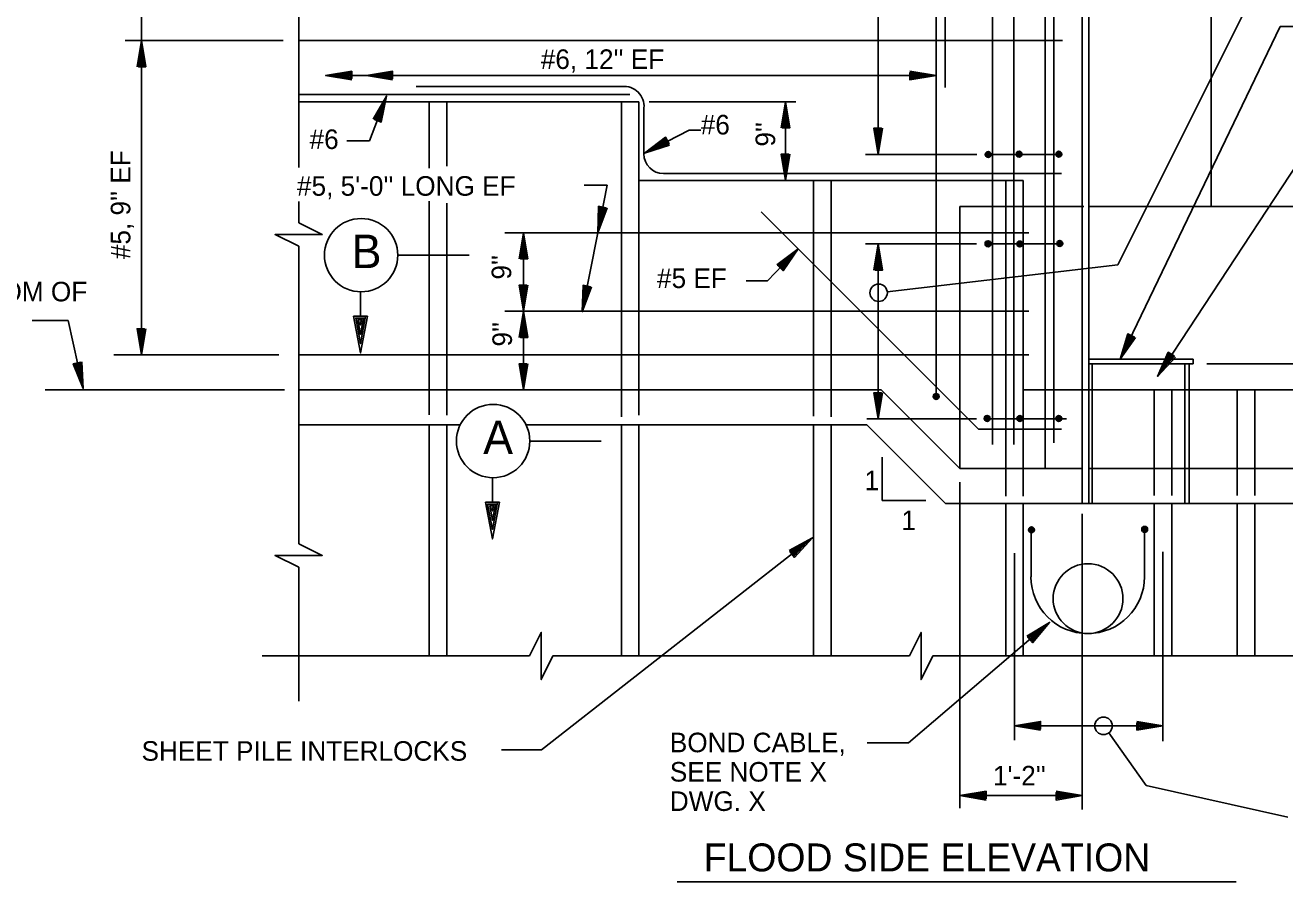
# Model space of a CAD drawing. Extents: x 22369.6 to 22428.3, y 22369.6 to 22415.
# Drawn here: x 22390.66 to 22402.68, y 22392.31 to 22400.49 of the extents above; entities that cross this region are included whole.
import ezdxf

# ---------------------------------------------------------------- set-up
doc = ezdxf.new("R2010")
doc.units = 0
for name, color, linetype in [('Level 1', 7, 'Continuous'), ('Level 10', 7, 'Continuous'), ('Level 2', 7, 'Continuous'), ('Level 3', 7, 'Continuous'), ('Level 4', 7, 'Continuous'), ('Level 7', 7, 'Continuous')]:
    doc.layers.add(name, color=color, linetype=linetype)

msp = doc.modelspace()

# ---------------------------------------------------------------- linework, layer by layer
at = {"layer": 'Level 1'}
for p, q in [((22398.803, 22399.253), (22398.803, 22404.537)), ((22393.273, 22402.402), (22393.273, 22399.126)), ((22401.087, 22398.198), (22402.551, 22401.125)), ((22391.773, 22400.339), (22391.773, 22400.88)), ((22401.112, 22397.297), (22402.638, 22400.474)), ((22402.638, 22400.474), (22403.065, 22400.474)), ((22393.126, 22400.339), (22391.617, 22400.339)), ((22391.773, 22397.339), (22391.773, 22400.339)), ((22391.773, 22400.339), (22391.773, 22400.339)), ((22391.773, 22400.269), (22391.773, 22400.269)), ((22393.53, 22400.005), (22393.53, 22400.005)), ((22393.53, 22400.005), (22399.355, 22400.005)), ((22393.6, 22400.005), (22393.6, 22400.005)), ((22394.125, 22400.005), (22394.125, 22400.005)), ((22394.148, 22400.02), (22394.148, 22400.02)), ((22394.148, 22400.001), (22394.148, 22400.001)), ((22394.158, 22400.033), (22394.158, 22400.033)), ((22394.158, 22399.988), (22394.158, 22399.988)), ((22394.169, 22400.046), (22394.169, 22400.046)), ((22394.169, 22399.976), (22394.169, 22399.976)), ((22394.169, 22399.964), (22394.169, 22399.964)), ((22399.285, 22400.005), (22399.285, 22400.005)), ((22399.355, 22400.005), (22399.355, 22400.005)), ((22401.468, 22397.133), (22403.245, 22399.842)), ((22393.949, 22399.381), (22394.111, 22399.809)), ((22394.086, 22399.744), (22394.086, 22399.744)), ((22394.111, 22399.809), (22394.111, 22399.809)), ((22396.616, 22399.755), (22398.017, 22399.755)), ((22397.918, 22399.005), (22397.918, 22399.755)), ((22397.918, 22399.755), (22397.918, 22399.755)), ((22397.918, 22399.686), (22397.918, 22399.686)), ((22396.571, 22399.265), (22396.999, 22399.485)), ((22396.999, 22399.485), (22397.109, 22399.485)), ((22393.731, 22399.381), (22393.949, 22399.381)), ((22396.571, 22399.265), (22396.571, 22399.265)), ((22396.633, 22399.297), (22396.633, 22399.297)), ((22399.743, 22399.253), (22398.681, 22399.253)), ((22398.803, 22399.323), (22398.803, 22399.323)), ((22398.803, 22399.253), (22398.803, 22399.253)), ((22397.918, 22399.075), (22397.918, 22399.075)), ((22397.918, 22399.005), (22397.918, 22399.005)), ((22395.998, 22398.959), (22396.217, 22398.959)), ((22396.127, 22398.505), (22396.217, 22398.959)), ((22393.273, 22398.6), (22393.273, 22398.804)), ((22396.141, 22398.573), (22396.141, 22398.573)), ((22395.418, 22397.755), (22395.418, 22398.505)), ((22395.418, 22398.505), (22395.418, 22398.505)), ((22395.418, 22398.436), (22395.418, 22398.436)), ((22395.979, 22397.751), (22396.127, 22398.505)), ((22396.127, 22398.505), (22396.127, 22398.505)), ((22399.739, 22398.399), (22398.681, 22398.399)), ((22398.803, 22396.729), (22398.803, 22398.399)), ((22398.803, 22398.399), (22398.803, 22398.399)), ((22393.273, 22395.537), (22393.273, 22398.376)), ((22397.747, 22398.046), (22398.037, 22398.351)), ((22397.989, 22398.301), (22397.989, 22398.301)), ((22398.037, 22398.351), (22398.037, 22398.351)), ((22398.803, 22398.329), (22398.803, 22398.329)), ((22398.889, 22397.941), (22401.087, 22398.198)), ((22397.542, 22398.046), (22397.747, 22398.046)), ((22395.418, 22397.825), (22395.418, 22397.825)), ((22395.992, 22397.819), (22395.992, 22397.819)), ((22395.418, 22397.005), (22395.418, 22397.755)), ((22395.418, 22397.755), (22395.418, 22397.755)), ((22395.418, 22397.755), (22395.418, 22397.755)), ((22395.418, 22397.686), (22395.418, 22397.686)), ((22395.979, 22397.751), (22395.979, 22397.751)), ((22390.732, 22397.666), (22391.074, 22397.666)), ((22391.074, 22397.666), (22391.217, 22397.019)), ((22393.083, 22397.339), (22391.508, 22397.339)), ((22391.773, 22397.408), (22391.773, 22397.408)), ((22391.773, 22397.339), (22391.773, 22397.339)), ((22401.142, 22397.36), (22401.142, 22397.36)), ((22400.811, 22397.297), (22401.807, 22397.297)), ((22400.811, 22397.255), (22401.807, 22397.255)), ((22400.843, 22395.922), (22400.843, 22397.255)), ((22401.112, 22397.297), (22401.112, 22397.297)), ((22401.506, 22397.191), (22401.506, 22397.191)), ((22401.728, 22395.922), (22401.728, 22397.255)), ((22401.769, 22395.922), (22401.769, 22397.255)), ((22401.807, 22397.255), (22401.807, 22397.297)), ((22401.938, 22397.255), (22404.364, 22397.255)), ((22391.202, 22397.087), (22391.202, 22397.087)), ((22395.418, 22397.075), (22395.418, 22397.075)), ((22401.468, 22397.133), (22401.468, 22397.133)), ((22393.137, 22397.005), (22390.853, 22397.005)), ((22391.217, 22397.019), (22391.217, 22397.019)), ((22395.418, 22397.005), (22395.418, 22397.005)), ((22399.739, 22396.729), (22398.693, 22396.729)), ((22398.803, 22396.798), (22398.803, 22396.798)), ((22398.803, 22396.729), (22398.803, 22396.729)), ((22399.582, 22396.123), (22399.582, 22393.012)), ((22400.749, 22395.821), (22400.749, 22393.002)), ((22395.59, 22393.569), (22398.174, 22395.594)), ((22398.12, 22395.551), (22398.12, 22395.551)), ((22398.174, 22395.594), (22398.174, 22395.594)), ((22400.103, 22395.447), (22400.103, 22393.662)), ((22401.519, 22395.459), (22401.519, 22393.652)), ((22393.273, 22394.036), (22393.273, 22395.313)), ((22400.437, 22394.786), (22399.09, 22393.636)), ((22400.384, 22394.741), (22400.384, 22394.741)), ((22400.437, 22394.786), (22400.437, 22394.786)), ((22392.926, 22394.466), (22395.475, 22394.466)), ((22395.699, 22394.466), (22399.1, 22394.466)), ((22399.324, 22394.466), (22405.542, 22394.466)), ((22400.103, 22393.799), (22401.519, 22393.799)), ((22400.103, 22393.799), (22400.103, 22393.799)), ((22400.172, 22393.799), (22400.172, 22393.799)), ((22401.001, 22393.732), (22401.36, 22393.23)), ((22401.45, 22393.799), (22401.45, 22393.799)), ((22401.519, 22393.799), (22401.519, 22393.799)), ((22398.697, 22393.636), (22399.09, 22393.636)), ((22395.209, 22393.569), (22395.59, 22393.569)), ((22401.36, 22393.23), (22402.709, 22392.927)), ((22399.582, 22393.133), (22400.749, 22393.133)), ((22399.582, 22393.133), (22399.582, 22393.133)), ((22399.651, 22393.133), (22399.651, 22393.133)), ((22400.679, 22393.133), (22400.679, 22393.133)), ((22400.749, 22393.133), (22400.749, 22393.133))]:
    msp.add_line(p, q, dxfattribs=at)
for points in [[(22391.732, 22400.089), (22391.773, 22400.339), (22391.814, 22400.089), (22391.744, 22400.089), (22391.773, 22400.269), (22391.801, 22400.1), (22391.756, 22400.1), (22391.773, 22400.203), (22391.788, 22400.111), (22391.769, 22400.111), (22391.773, 22400.133)], [(22393.78, 22399.964), (22393.53, 22400.005), (22393.78, 22400.046), (22393.78, 22399.976), (22393.6, 22400.005), (22393.769, 22400.033), (22393.769, 22399.988), (22393.666, 22400.005), (22393.758, 22400.02), (22393.758, 22400.001), (22393.736, 22400.005)], [(22394.169, 22399.964), (22393.92, 22400.005), (22394.169, 22400.046), (22394.169, 22399.976), (22393.989, 22400.005), (22394.158, 22400.033), (22394.158, 22399.988), (22394.056, 22400.005), (22394.148, 22400.02), (22394.148, 22400.001), (22394.125, 22400.005)], [(22399.105, 22400.046), (22399.355, 22400.005), (22399.105, 22399.964), (22399.105, 22400.034), (22399.285, 22400.005), (22399.116, 22399.977), (22399.116, 22400.022), (22399.219, 22400.005), (22399.127, 22399.99), (22399.127, 22400.009), (22399.149, 22400.005)], [(22393.984, 22399.59), (22394.111, 22399.809), (22394.061, 22399.561), (22393.995, 22399.586), (22394.086, 22399.744), (22394.053, 22399.576), (22394.01, 22399.592), (22394.063, 22399.682), (22394.044, 22399.591), (22394.027, 22399.597), (22394.038, 22399.617)], [(22397.877, 22399.506), (22397.918, 22399.755), (22397.959, 22399.506), (22397.889, 22399.506), (22397.918, 22399.686), (22397.946, 22399.517), (22397.901, 22399.517), (22397.918, 22399.619), (22397.933, 22399.527), (22397.914, 22399.527), (22397.918, 22399.55)], [(22398.844, 22399.503), (22398.803, 22399.253), (22398.761, 22399.503), (22398.832, 22399.503), (22398.803, 22399.323), (22398.775, 22399.492), (22398.82, 22399.492), (22398.803, 22399.389), (22398.788, 22399.481), (22398.807, 22399.481), (22398.803, 22399.459)], [(22396.812, 22399.342), (22396.571, 22399.265), (22396.774, 22399.416), (22396.807, 22399.353), (22396.633, 22399.297), (22396.771, 22399.399), (22396.792, 22399.359), (22396.692, 22399.327), (22396.767, 22399.382), (22396.776, 22399.366), (22396.754, 22399.359)], [(22397.959, 22399.255), (22397.918, 22399.005), (22397.877, 22399.255), (22397.947, 22399.255), (22397.918, 22399.075), (22397.89, 22399.244), (22397.935, 22399.244), (22397.918, 22399.141), (22397.903, 22399.233), (22397.922, 22399.233), (22397.918, 22399.211)], [(22396.216, 22398.742), (22396.127, 22398.505), (22396.135, 22398.758), (22396.204, 22398.744), (22396.141, 22398.573), (22396.146, 22398.745), (22396.19, 22398.736), (22396.154, 22398.639), (22396.157, 22398.732), (22396.175, 22398.728), (22396.167, 22398.707)], [(22393.273, 22398.376), (22393.048, 22398.487), (22393.498, 22398.487), (22393.273, 22398.6)], [(22395.377, 22398.256), (22395.418, 22398.505), (22395.459, 22398.256), (22395.389, 22398.256), (22395.418, 22398.436), (22395.446, 22398.267), (22395.401, 22398.267), (22395.418, 22398.369), (22395.433, 22398.277), (22395.414, 22398.277), (22395.418, 22398.3)], [(22398.761, 22398.149), (22398.803, 22398.399), (22398.844, 22398.149), (22398.773, 22398.149), (22398.803, 22398.329), (22398.831, 22398.16), (22398.785, 22398.16), (22398.803, 22398.263), (22398.817, 22398.171), (22398.799, 22398.171), (22398.803, 22398.193)], [(22397.835, 22398.199), (22398.037, 22398.351), (22397.895, 22398.142), (22397.844, 22398.191), (22397.989, 22398.301), (22397.893, 22398.159), (22397.86, 22398.19), (22397.943, 22398.253), (22397.891, 22398.176), (22397.877, 22398.189), (22397.896, 22398.202)], [(22395.459, 22398.005), (22395.418, 22397.755), (22395.377, 22398.005), (22395.447, 22398.005), (22395.418, 22397.825), (22395.39, 22397.994), (22395.435, 22397.994), (22395.418, 22397.891), (22395.403, 22397.983), (22395.422, 22397.983), (22395.418, 22397.961)], [(22396.068, 22397.988), (22395.979, 22397.751), (22395.986, 22398.004), (22396.056, 22397.99), (22395.992, 22397.819), (22395.997, 22397.991), (22396.042, 22397.982), (22396.005, 22397.885), (22396.008, 22397.978), (22396.027, 22397.974), (22396.018, 22397.953)], [(22395.377, 22397.506), (22395.418, 22397.755), (22395.459, 22397.506), (22395.389, 22397.506), (22395.418, 22397.686), (22395.446, 22397.517), (22395.401, 22397.517), (22395.418, 22397.619), (22395.433, 22397.527), (22395.414, 22397.527), (22395.418, 22397.55)], [(22391.814, 22397.588), (22391.773, 22397.339), (22391.732, 22397.588), (22391.802, 22397.588), (22391.773, 22397.408), (22391.745, 22397.577), (22391.79, 22397.577), (22391.773, 22397.475), (22391.758, 22397.567), (22391.777, 22397.567), (22391.773, 22397.544)], [(22401.258, 22397.504), (22401.112, 22397.297), (22401.183, 22397.54), (22401.247, 22397.509), (22401.142, 22397.36), (22401.191, 22397.524), (22401.231, 22397.505), (22401.171, 22397.42), (22401.198, 22397.509), (22401.215, 22397.501), (22401.201, 22397.482)], [(22401.639, 22397.319), (22401.468, 22397.133), (22401.57, 22397.364), (22401.629, 22397.326), (22401.506, 22397.191), (22401.575, 22397.348), (22401.613, 22397.323), (22401.542, 22397.247), (22401.58, 22397.332), (22401.596, 22397.322), (22401.58, 22397.305)], [(22391.203, 22397.272), (22391.217, 22397.019), (22391.123, 22397.254), (22391.192, 22397.269), (22391.202, 22397.087), (22391.138, 22397.246), (22391.182, 22397.256), (22391.187, 22397.152), (22391.153, 22397.239), (22391.172, 22397.243), (22391.172, 22397.22)], [(22395.459, 22397.255), (22395.418, 22397.005), (22395.377, 22397.255), (22395.447, 22397.255), (22395.418, 22397.075), (22395.39, 22397.244), (22395.435, 22397.244), (22395.418, 22397.141), (22395.403, 22397.233), (22395.422, 22397.233), (22395.418, 22397.211)], [(22398.844, 22396.978), (22398.803, 22396.729), (22398.761, 22396.978), (22398.832, 22396.978), (22398.803, 22396.798), (22398.775, 22396.968), (22398.82, 22396.968), (22398.803, 22396.865), (22398.788, 22396.957), (22398.807, 22396.957), (22398.803, 22396.934)], [(22393.273, 22395.313), (22393.048, 22395.425), (22393.498, 22395.425), (22393.273, 22395.537)], [(22397.953, 22395.473), (22398.174, 22395.594), (22398.004, 22395.407), (22397.96, 22395.463), (22398.12, 22395.551), (22398.004, 22395.425), (22397.976, 22395.46), (22398.067, 22395.51), (22398.004, 22395.442), (22397.992, 22395.456), (22398.013, 22395.467)], [(22395.699, 22394.466), (22395.587, 22394.241), (22395.587, 22394.69), (22395.475, 22394.466)], [(22399.324, 22394.466), (22399.212, 22394.241), (22399.212, 22394.69), (22399.1, 22394.466)], [(22400.22, 22394.655), (22400.437, 22394.786), (22400.274, 22394.592), (22400.228, 22394.646), (22400.384, 22394.741), (22400.273, 22394.609), (22400.244, 22394.644), (22400.333, 22394.697), (22400.273, 22394.627), (22400.261, 22394.641), (22400.28, 22394.652)], [(22400.352, 22393.758), (22400.103, 22393.799), (22400.352, 22393.841), (22400.352, 22393.77), (22400.172, 22393.799), (22400.341, 22393.827), (22400.341, 22393.782), (22400.239, 22393.799), (22400.331, 22393.814), (22400.331, 22393.795), (22400.308, 22393.799)], [(22401.27, 22393.841), (22401.519, 22393.799), (22401.27, 22393.758), (22401.27, 22393.829), (22401.45, 22393.799), (22401.281, 22393.771), (22401.281, 22393.817), (22401.383, 22393.799), (22401.291, 22393.785), (22401.291, 22393.803), (22401.314, 22393.799)], [(22399.831, 22393.091), (22399.582, 22393.133), (22399.831, 22393.174), (22399.831, 22393.103), (22399.651, 22393.133), (22399.821, 22393.161), (22399.821, 22393.115), (22399.718, 22393.133), (22399.81, 22393.147), (22399.81, 22393.129), (22399.787, 22393.133)], [(22400.499, 22393.174), (22400.749, 22393.133), (22400.499, 22393.091), (22400.499, 22393.162), (22400.679, 22393.133), (22400.51, 22393.105), (22400.51, 22393.15), (22400.613, 22393.133), (22400.521, 22393.118), (22400.521, 22393.137), (22400.543, 22393.133)]]:
    msp.add_lwpolyline(points, dxfattribs=at)
for centre in [(22398.806, 22397.932), (22400.952, 22393.799)]:
    msp.add_circle(centre, 0.0833, dxfattribs=at)
at = {"layer": 'Level 10'}
for p, q in [((22399.442, 22399.89), (22399.442, 22404.422)), ((22399.894, 22396.483), (22399.894, 22404.422)), ((22400.096, 22396.483), (22400.096, 22404.422)), ((22400.478, 22396.499), (22400.478, 22404.422)), ((22399.355, 22396.937), (22399.355, 22401.367)), ((22400.561, 22400.339), (22393.273, 22400.339)), ((22396.38, 22399.9), (22394.393, 22399.9)), ((22396.433, 22399.823), (22393.273, 22399.823)), ((22396.567, 22399.257), (22396.567, 22399.696)), ((22400.561, 22399.253), (22399.859, 22399.253)), ((22400.55, 22399.069), (22396.755, 22399.069)), ((22400.811, 22398.755), (22407.215, 22398.755)), ((22399.758, 22396.63), (22397.684, 22398.704)), ((22400.239, 22398.505), (22395.239, 22398.505)), ((22399.862, 22398.399), (22400.561, 22398.399)), ((22400.239, 22397.755), (22395.239, 22397.755)), ((22400.239, 22397.339), (22393.273, 22397.339)), ((22398.832, 22397.005), (22393.273, 22397.005)), ((22399.582, 22396.255), (22398.832, 22397.005)), ((22399.859, 22396.729), (22400.599, 22396.729)), ((22394.815, 22396.672), (22393.273, 22396.672)), ((22398.694, 22396.672), (22395.442, 22396.672)), ((22399.444, 22395.922), (22398.694, 22396.672)), ((22400.55, 22396.63), (22399.758, 22396.63)), ((22400.749, 22396.255), (22399.582, 22396.255)), ((22400.811, 22396.255), (22405.818, 22396.255)), ((22400.811, 22395.922), (22399.444, 22395.922)), ((22400.811, 22395.922), (22407.215, 22395.922)), ((22400.26, 22395.222), (22400.26, 22395.672)), ((22401.343, 22395.222), (22401.343, 22395.672)), ((22396.883, 22392.31), (22402.217, 22392.31))]:
    msp.add_line(p, q, dxfattribs=at)
msp.add_circle((22400.804, 22395.013), 0.333, dxfattribs=at)
for centre, radius, start, end in [((22396.38, 22399.713), 0.188, 354.6989, 96.012), ((22396.755, 22399.257), 0.188, 180, 270), ((22400.801, 22395.222), 0.542, 180, 0)]:
    msp.add_arc(centre, radius, start, end, dxfattribs=at)
at = {"layer": 'Level 2'}
for p, q in [((22401.978, 22398.755), (22401.978, 22404.422)), ((22396.519, 22399.755), (22393.273, 22399.755)), ((22394.519, 22399.12), (22394.519, 22399.755)), ((22394.686, 22399.139), (22394.686, 22399.755)), ((22396.353, 22396.749), (22396.353, 22399.755)), ((22396.519, 22396.765), (22396.519, 22399.755)), ((22400.186, 22399.005), (22396.519, 22399.005)), ((22398.186, 22396.753), (22398.186, 22399.005)), ((22398.353, 22396.749), (22398.353, 22399.005)), ((22400.019, 22395.991), (22400.019, 22399.005)), ((22400.186, 22395.991), (22400.186, 22399.005)), ((22394.519, 22396.768), (22394.519, 22398.806)), ((22394.686, 22396.765), (22394.686, 22398.787)), ((22399.582, 22398.755), (22400.764, 22398.755)), ((22399.582, 22396.255), (22399.582, 22398.755)), ((22400.186, 22397.005), (22407.215, 22397.005)), ((22401.436, 22395.996), (22401.436, 22397.005)), ((22401.603, 22395.996), (22401.603, 22397.005)), ((22402.228, 22395.996), (22402.228, 22397.005)), ((22402.394, 22395.996), (22402.394, 22397.005)), ((22398.841, 22395.949), (22398.841, 22396.364)), ((22399.769, 22396.255), (22399.769, 22396.255)), ((22398.841, 22395.949), (22399.256, 22395.949))]:
    msp.add_line(p, q, dxfattribs=at)
for centre, radius in [((22399.851, 22399.252), 0.0281), ((22399.851, 22399.252), 0.0176), ((22399.851, 22399.252), 0.00703), ((22400.146, 22399.255), 0.0281), ((22400.146, 22399.255), 0.0176), ((22400.146, 22399.255), 0.00703), ((22400.526, 22399.255), 0.0281), ((22400.526, 22399.255), 0.0176), ((22400.526, 22399.255), 0.00703), ((22399.85, 22398.4), 0.0281), ((22399.85, 22398.4), 0.0176), ((22399.85, 22398.4), 0.00703), ((22400.153, 22398.398), 0.0281), ((22400.153, 22398.398), 0.0176), ((22400.153, 22398.398), 0.00703), ((22400.534, 22398.403), 0.0281), ((22400.534, 22398.403), 0.0176), ((22400.534, 22398.403), 0.00703), ((22399.355, 22396.943), 0.0281), ((22399.355, 22396.943), 0.0176), ((22399.355, 22396.943), 0.00703), ((22399.841, 22396.733), 0.0281), ((22399.841, 22396.733), 0.0176), ((22399.841, 22396.733), 0.00703), ((22400.153, 22396.732), 0.0281), ((22400.153, 22396.732), 0.0176), ((22400.153, 22396.732), 0.00703), ((22400.526, 22396.732), 0.0281), ((22400.526, 22396.732), 0.0176), ((22400.526, 22396.732), 0.00703), ((22400.265, 22395.67), 0.0281), ((22400.265, 22395.67), 0.0176), ((22400.265, 22395.67), 0.00703), ((22401.344, 22395.674), 0.0281), ((22401.344, 22395.674), 0.0176), ((22401.344, 22395.674), 0.00703)]:
    msp.add_circle(centre, radius, dxfattribs=at)
at = {"layer": 'Level 3'}
for p, q in [((22394.9, 22398.291), (22394.212, 22398.291)), ((22393.863, 22397.708), (22393.863, 22397.941)), ((22396.16, 22396.517), (22395.471, 22396.517)), ((22395.122, 22395.933), (22395.122, 22396.167))]:
    msp.add_line(p, q, dxfattribs=at)
for points in [[(22393.912, 22397.708), (22393.929, 22397.708), (22393.863, 22397.358), (22393.797, 22397.708), (22393.912, 22397.708), (22393.864, 22397.447), (22393.817, 22397.691), (22393.892, 22397.691), (22393.864, 22397.535), (22393.838, 22397.675), (22393.873, 22397.675), (22393.864, 22397.624), (22393.857, 22397.658)], [(22395.171, 22395.933), (22395.188, 22395.933), (22395.122, 22395.583), (22395.056, 22395.933), (22395.171, 22395.933), (22395.123, 22395.673), (22395.076, 22395.916), (22395.152, 22395.916), (22395.123, 22395.761), (22395.097, 22395.9), (22395.132, 22395.9), (22395.123, 22395.85), (22395.117, 22395.883)]]:
    msp.add_lwpolyline(points, dxfattribs=at)
for centre in [(22393.869, 22398.291), (22395.128, 22396.517)]:
    msp.add_circle(centre, 0.35, dxfattribs=at)
at = {"layer": 'Level 7'}
for p, q in [((22400.394, 22396.255), (22400.394, 22404.422)), ((22400.749, 22395.922), (22400.749, 22404.422)), ((22400.811, 22395.922), (22400.811, 22404.422)), ((22394.519, 22396.672), (22394.519, 22394.466)), ((22394.686, 22396.672), (22394.686, 22394.466)), ((22396.353, 22396.672), (22396.353, 22394.466)), ((22396.519, 22396.672), (22396.519, 22394.466)), ((22398.186, 22396.672), (22398.186, 22394.466)), ((22398.353, 22396.672), (22398.353, 22394.466)), ((22400.019, 22395.922), (22400.019, 22394.466)), ((22400.186, 22395.922), (22400.186, 22394.466)), ((22401.436, 22395.922), (22401.436, 22394.466)), ((22401.603, 22395.922), (22401.603, 22394.466)), ((22402.228, 22395.922), (22402.228, 22394.466)), ((22402.394, 22395.922), (22402.394, 22394.466))]:
    msp.add_line(p, q, dxfattribs=at)

# ---------------------------------------------------------------- texts
at = {"layer": 'Level 10'}
msp.add_text('FLOOD SIDE ELEVATION', height=0.2667, dxfattribs=at).set_placement((22397.137, 22392.41))
at = {"layer": 'Level 3'}
for s, p in [('B', (22393.778, 22398.167)), ('A', (22395.033, 22396.392))]:
    msp.add_text(s, height=0.32, dxfattribs=at).set_placement(p)
at = {"layer": 'Level 4'}
for s, height, p in [("#6, 12'' EF", 0.18667, (22395.583, 22400.068)), ('#6', 0.1867, (22397.109, 22399.443)), ('#6', 0.1867, (22393.377, 22399.304)), ("#5, 5'-0'' LONG EF", 0.18667, (22393.257, 22398.858)), ('#5 EF', 0.1867, (22396.692, 22397.977)), ('BOTTOM OF', 0.1867, (22389.772, 22397.85)), ('1', 0.187, (22398.672, 22396.048)), ('1', 0.187, (22399.024, 22395.667)), ('BOND CABLE,', 0.18667, (22396.814, 22393.547)), ('SHEET PILE INTERLOCKS', 0.18667, (22391.774, 22393.466)), ('SEE NOTE X', 0.1867, (22396.814, 22393.267)), ("1'-2''", 0.1867, (22399.897, 22393.23)), ('DWG. X', 0.1867, (22396.814, 22392.987))]:
    msp.add_text(s, height=height, dxfattribs=at).set_placement(p)
for s, p in [("9''", (22397.819, 22399.327)), ("#5, 9'' EF", (22391.667, 22398.253)), ("9''", (22395.301, 22398.058)), ("9''", (22395.308, 22397.419))]:
    msp.add_text(s, height=0.1867, rotation=90, dxfattribs=at).set_placement(p)

doc.saveas('drawing.dxf')
